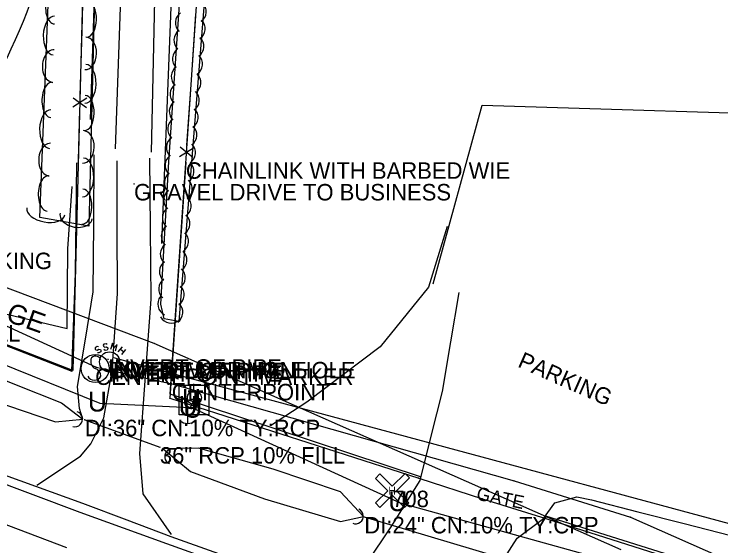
# Model space of a CAD drawing. Extents: x 1441650 to 1491889, y 345904 to 358319.
# Drawn here: x 1445767.6 to 1445982.1, y 354579.8 to 354741.3 of the extents above; entities that cross this region are included whole.
import ezdxf

# ---------------------------------------------------------------- set-up
doc = ezdxf.new("R2010")
doc.units = 0
for name, color, linetype in [('Default', 7, 'Continuous'), ('S_CROSS_DRAIN', 7, 'Continuous'), ('S_CROSS_DRAIN_ANNOT', 7, 'Continuous'), ('S_DITCHLINE', 7, 'Continuous'), ('S_DRG_PT_SYM', 7, 'Continuous'), ('S_EDGE_PAVEMENT', 7, 'Continuous'), ('S_FENCE', 7, 'Continuous'), ('S_FENCE_ANNOT', 7, 'Continuous'), ('S_GAS_UTILITIES', 7, 'Continuous'), ('S_GAS_UTILITIES_ANNOT', 7, 'Continuous'), ('S_GATE_ANNOT', 7, 'Continuous'), ('S_GRAVEL_ROAD', 7, 'Continuous'), ('S_MANHOLE_ANNOT', 7, 'Continuous'), ('S_MISC_BOUNDARY_ANNOT', 7, 'Continuous'), ('S_MSC_PT_SYM', 7, 'Continuous'), ('S_PARKING', 7, 'Continuous'), ('S_PARKING_ANNOT', 7, 'Continuous'), ('S_PAVEMENT_CROWN', 7, 'Continuous'), ('S_PHOTO_CTL', 7, 'Continuous'), ('S_PHOTO_CTL_ANNOT', 7, 'Continuous'), ('S_SANITARY_SEWER', 7, 'Continuous'), ('S_SANITARY_SEWER_ANNOT', 7, 'Continuous'), ('S_SHOULDER', 7, 'Continuous'), ('S_SIGN', 7, 'Continuous'), ('S_SIGN_ANNOT', 7, 'Continuous'), ('S_STREAM', 7, 'Continuous'), ('S_SURVEY_TEXT_ANNOT', 7, 'Continuous'), ('S_TELEPHONE_UTILITIES', 7, 'Continuous'), ('S_TREE', 7, 'Continuous'), ('S_UNDERGROUND_CABLE', 7, 'Continuous'), ('S_UTILITY_POLE', 7, 'Continuous'), ('S_UTL_PT_SYM', 7, 'Continuous'), ('S_WATER_UTILITIES', 7, 'Continuous')]:
    doc.layers.add(name, color=color, linetype=linetype)

msp = doc.modelspace()

# ---------------------------------------------------------------- linework, layer by layer
at = {"layer": 'S_CROSS_DRAIN'}
for p, q in [((1445789.02, 354618.12), (1445811.83, 354609.8)), ((1445873.89, 354588.6), (1445920.32, 354574.73))]:
    msp.add_line(p, q, dxfattribs=at)
for centre, start, end in [((1445786.07, 354618.31), 254.2844, 74.6136), ((1445815.59, 354606.93), 68.2155, 248.5447), ((1445871.28, 354588.81), 246.6814, 67.0106)]:
    msp.add_arc(centre, 2.3, start, end, dxfattribs=at)
at = {"layer": 'S_DITCHLINE'}
for points in [[(1445788.43, 354618.25), (1445787.46, 354621.49), (1445786.82, 354628.25), (1445789.21, 354642.59), (1445791.61, 354656.92), (1445791.77, 354677.73), (1445791.93, 354698.55)], [(1445718.48, 354646.49), (1445724.35, 354644.58), (1445738.95, 354639.6), (1445753.55, 354634.61), (1445767.74, 354628.93), (1445781.94, 354623.24), (1445788.45, 354618.24)], [(1445718.49, 354646.49), (1445722.92, 354641.68), (1445736.93, 354634.55), (1445750.94, 354627.42), (1445765.53, 354622.43), (1445780.12, 354617.44), (1445788.4, 354618.25)]]:
    msp.add_lwpolyline(points, dxfattribs=at)
msp.add_lwpolyline([(1445812.85, 354609.24), (1445821.09, 354602.4), (1445843.54, 354594.09), (1445866.61, 354587.17), (1445873.64, 354588.7), (1445866.68, 354596.26), (1445846.24, 354603.09), (1445823.57, 354609.53)], close=True, dxfattribs=at)
at = {"layer": 'S_DRG_PT_SYM'}
for points in [[(1445789.02, 354618.12), (1445789.02, 354618.17), (1445789.02, 354618.12), (1445788.97, 354618.12), (1445789.02, 354618.12), (1445789.02, 354618.07), (1445789.02, 354618.12), (1445789.07, 354618.12)], [(1445811.83, 354609.8), (1445811.83, 354609.85), (1445811.83, 354609.8), (1445811.78, 354609.8), (1445811.83, 354609.8), (1445811.83, 354609.75), (1445811.83, 354609.8), (1445811.88, 354609.8)], [(1445873.89, 354588.6), (1445873.89, 354588.65), (1445873.89, 354588.6), (1445873.84, 354588.6), (1445873.89, 354588.6), (1445873.89, 354588.55), (1445873.89, 354588.6), (1445873.94, 354588.6)]]:
    msp.add_lwpolyline(points, dxfattribs=at)
at = {"layer": 'S_EDGE_PAVEMENT'}
msp.add_lwpolyline([(1445758.93, 354600.82), (1445773.25, 354595.45), (1445787.57, 354590.09), (1445800.71, 354585.31), (1445813.85, 354580.52), (1445828.54, 354575.32)], dxfattribs=at)
at = {"layer": 'S_FENCE'}
for p, q in [((1445789.61, 354715.73), (1445785.44, 354712.97)), ((1445785.51, 354715.84), (1445789.53, 354712.87)), ((1445817.79, 354698.06), (1445822.07, 354700.64)), ((1445821.87, 354697.78), (1445817.98, 354700.92)), ((1445819.73, 354696.27), (1445814.87, 354624.65)), ((1445786.23, 354662.58), (1445786.63, 354696.05)), ((1445785.12, 354632.89), (1445786.23, 354662.58)), ((1445717.1, 354659.39), (1445785.12, 354632.89)), ((1445814.87, 354624.65), (1445890.4, 354600.42)), ((1445890.4, 354600.42), (1445909.74, 354594.09)), ((1445909.74, 354594.09), (1445929.03, 354588.1)), ((1445929.03, 354588.1), (1446032.54, 354555.34))]:
    msp.add_line(p, q, dxfattribs=at)
for points in [[(1445790.41, 354824.29), (1445785.39, 354633.02), (1445717.16, 354659.61)], [(1445891.24, 354600.72), (1445814.94, 354625.84), (1445824.57, 354767.69), (1445980.66, 354766.35)], [(1445788.62, 354756.33), (1445788.1, 354736.34)], [(1445821.42, 354721.3), (1445822.77, 354741.25)], [(1445788.1, 354736.34), (1445787.57, 354716.35)], [(1445820.06, 354701.34), (1445821.42, 354721.3)], [(1445787.47, 354712.35), (1445787.06, 354696.95)], [(1446086.26, 354539.37), (1445928.95, 354588.88)]]:
    msp.add_lwpolyline(points, dxfattribs=at)
at = {"layer": 'S_GAS_UTILITIES'}
for p, q in [((1445467.8, 354783.19), (1445792.48, 354634.07)), ((1445792.48, 354634.07), (1445815.43, 354629)), ((1445815.43, 354629), (1445919.33, 354599.56)), ((1445919.33, 354599.56), (1445954.67, 354588.57)), ((1445954.67, 354588.57), (1445989.77, 354573.1))]:
    msp.add_line(p, q, dxfattribs=at)
at = {"layer": 'S_GRAVEL_ROAD'}
for points in [[(1445809.25, 354699.37), (1445810.78, 354768.8), (1445812.32, 354864.17)], [(1445802.23, 354856.45), (1445800.36, 354760.69), (1445798.21, 354700.41)], [(1445774.44, 354598.22), (1445787.76, 354607.08), (1445790.89, 354610.81), (1445794.79, 354618.66), (1445797.37, 354633.08), (1445798.94, 354656.43), (1445798.88, 354676.57), (1445798.82, 354696.71)], [(1445815.36, 354583.24), (1445806.71, 354595.59), (1445805.78, 354607.86), (1445807.46, 354631.31), (1445809.15, 354654.76), (1445808.95, 354676.16), (1445808.75, 354697.56)], [(1445718.48, 354666.76), (1445739.25, 354656.29), (1445761.44, 354651.06), (1445783.64, 354645.82), (1445783.92, 354670.01), (1445785.2, 354688.95)], [(1445866.75, 354564.96), (1445874.66, 354574.6), (1445882, 354585.59), (1445890.82, 354599.62), (1445894.2, 354613.15), (1445897.58, 354626.67), (1445900.15, 354641.73), (1445902.71, 354656.79)], [(1445919.97, 354547.38), (1445916.01, 354559.79), (1445916.32, 354575.94), (1445920.32, 354582.13), (1445928.28, 354588.08), (1445931.72, 354592.89), (1445938.4, 354594.75), (1445942.86, 354593.76), (1445956.94, 354590.17), (1445971.03, 354586.57), (1445985.12, 354582.98), (1445999.2, 354579.38), (1446018.14, 354575.85), (1446037.08, 354572.32), (1446051.94, 354570.3), (1446066.81, 354568.29), (1446081.67, 354566.27), (1446096.54, 354564.25), (1446111, 354561.07), (1446125.47, 354557.89)]]:
    msp.add_lwpolyline(points, dxfattribs=at)
at = {"layer": 'S_MSC_PT_SYM'}
for points in [[(1445786.63, 354696.05), (1445786.63, 354696.1), (1445786.63, 354696.05), (1445786.58, 354696.05), (1445786.63, 354696.05), (1445786.63, 354696), (1445786.63, 354696.05), (1445786.68, 354696.05)], [(1445819.73, 354696.27), (1445819.73, 354696.32), (1445819.73, 354696.27), (1445819.68, 354696.27), (1445819.73, 354696.27), (1445819.73, 354696.22), (1445819.73, 354696.27), (1445819.78, 354696.27)], [(1445803.99, 354689.7), (1445803.99, 354689.75), (1445803.99, 354689.7), (1445803.94, 354689.7), (1445803.99, 354689.7), (1445803.99, 354689.65), (1445803.99, 354689.7), (1445804.04, 354689.7)], [(1445786.23, 354662.58), (1445786.23, 354662.63), (1445786.23, 354662.58), (1445786.18, 354662.58), (1445786.23, 354662.58), (1445786.23, 354662.53), (1445786.23, 354662.58), (1445786.28, 354662.58)], [(1445785.12, 354632.89), (1445785.12, 354632.94), (1445785.12, 354632.89), (1445785.07, 354632.89), (1445785.12, 354632.89), (1445785.12, 354632.84), (1445785.12, 354632.89), (1445785.17, 354632.89)], [(1445814.87, 354624.65), (1445814.87, 354624.7), (1445814.87, 354624.65), (1445814.82, 354624.65), (1445814.87, 354624.65), (1445814.87, 354624.6), (1445814.87, 354624.65), (1445814.92, 354624.65)], [(1445890.4, 354600.42), (1445890.4, 354600.47), (1445890.4, 354600.42), (1445890.35, 354600.42), (1445890.4, 354600.42), (1445890.4, 354600.37), (1445890.4, 354600.42), (1445890.45, 354600.42)], [(1445909.74, 354594.09), (1445909.74, 354594.14), (1445909.74, 354594.09), (1445909.69, 354594.09), (1445909.74, 354594.09), (1445909.74, 354594.04), (1445909.74, 354594.09), (1445909.79, 354594.09)], [(1445929.03, 354588.1), (1445929.03, 354588.15), (1445929.03, 354588.1), (1445928.98, 354588.1), (1445929.03, 354588.1), (1445929.03, 354588.05), (1445929.03, 354588.1), (1445929.08, 354588.1)]]:
    msp.add_lwpolyline(points, dxfattribs=at)
at = {"layer": 'S_PARKING'}
msp.add_lwpolyline([(1445894.76, 354659.33), (1445909.68, 354713.61), (1446020.86, 354710.14)], dxfattribs=at)
msp.add_ellipse((1445590.08, 354813.05), major_axis=(128.22, 146.75), ratio=0.999981, start_param=4.605684, end_param=5.103888, dxfattribs=at)
at = {"layer": 'S_PAVEMENT_CROWN'}
msp.add_lwpolyline([(1445754.09, 354590.41), (1445768.79, 354584.89), (1445783.49, 354579.36)], dxfattribs=at)
at = {"layer": 'S_PHOTO_CTL'}
for p, q in [((1445877.25, 354600.31), (1445878.61, 354601.66)), ((1445878.61, 354601.66), (1445882.35, 354597.92)), ((1445882.35, 354597.92), (1445886.25, 354601.82)), ((1445886.25, 354601.82), (1445887.6, 354600.47)), ((1445880.99, 354596.57), (1445877.25, 354600.31)), ((1445887.6, 354600.47), (1445883.7, 354596.57)), ((1445877.25, 354592.84), (1445880.99, 354596.57)), ((1445883.7, 354596.57), (1445887.44, 354592.84)), ((1445882.34, 354595.22), (1445878.61, 354591.48)), ((1445886.08, 354591.48), (1445882.34, 354595.22)), ((1445878.61, 354591.48), (1445877.25, 354592.84)), ((1445887.44, 354592.84), (1445886.08, 354591.48))]:
    msp.add_line(p, q, dxfattribs=at)
at = {"layer": 'S_SANITARY_SEWER'}
for p, q in [((1445792.78, 354640.37), (1445792.23, 354639.98)), ((1445793.2, 354640.29), (1445792.78, 354640.37)), ((1445792.23, 354639.98), (1445792.16, 354639.59)), ((1445792.16, 354639.59), (1445792.35, 354639.32)), ((1445792.35, 354639.32), (1445792.78, 354639.21)), ((1445792.78, 354639.21), (1445793.32, 354639.55)), ((1445793.32, 354638.39), (1445792.93, 354638.47)), ((1445793.32, 354639.55), (1445793.78, 354639.48)), ((1445793.86, 354638.78), (1445793.32, 354638.39)), ((1445793.78, 354639.48), (1445793.94, 354639.21)), ((1445793.94, 354639.21), (1445793.86, 354638.78)), ((1445799.21, 354638.74), (1445800.45, 354640.21)), ((1445799.87, 354639.52), (1445800.84, 354638.7)), ((1445801.42, 354639.4), (1445800.18, 354637.93)), ((1445798.06, 354636.92), (1446371.19, 354482.39))]:
    msp.add_line(p, q, dxfattribs=at)
for points in [[(1445795.88, 354640.91), (1445795.53, 354641.18), (1445794.87, 354641.1), (1445794.64, 354640.76), (1445794.67, 354640.45), (1445795.02, 354640.14), (1445795.64, 354640.25), (1445796.03, 354639.94), (1445796.07, 354639.63), (1445795.8, 354639.24), (1445795.18, 354639.17), (1445794.83, 354639.44)], [(1445798.32, 354639.05), (1445798.86, 354640.91), (1445797.81, 354639.9), (1445797.43, 354641.34), (1445796.88, 354639.48)]]:
    msp.add_lwpolyline(points, dxfattribs=at)
msp.add_circle((1445796.56, 354635.68), 3.05, dxfattribs=at)
at = {"layer": 'S_SHOULDER'}
msp.add_lwpolyline([(1445759.69, 354603.15), (1445774.03, 354597.98), (1445788.37, 354592.81), (1445801.79, 354587.73), (1445815.2, 354582.66), (1445829.6, 354577.51)], dxfattribs=at)
at = {"layer": 'S_SIGN'}
msp.add_circle((1445792.2, 354633.68), 4.24, dxfattribs=at)
for centre, radius, start, end in [((1445793.37, 354635.93), 2.55, 167.1196, 241.9813), ((1445792.33, 354635.84), 1.62, 16.5258, 156.8957), ((1445791.5, 354631.4), 2.38, 358.6529, 73.7063), ((1445791.94, 354632.28), 2.17, 204.641, 335.359)]:
    msp.add_arc(centre, radius, start, end, dxfattribs=at)
at = {"layer": 'S_STREAM'}
for points in [[(1445790.79, 354709.29), (1445794.12, 354810.87)], [(1445812.41, 354671.58), (1445817.58, 354802.35)], [(1445899.02, 354676.78), (1445893.35, 354658.37), (1445878.66, 354640.27), (1445856.49, 354623.48), (1445845.71, 354616.47)]]:
    msp.add_lwpolyline(points, dxfattribs=at)
at = {"layer": 'S_TELEPHONE_UTILITIES'}
msp.add_lwpolyline([(1445817.65, 354619.57), (1445817.65, 354628.57), (1445826.65, 354628.57), (1445826.65, 354619.57)], close=True, dxfattribs=at)
at = {"layer": 'S_TREE'}
for points in [[(1446000.72, 354764.17), (1445826.85, 354765.13), (1445817.58, 354647.96), (1445813.11, 354648.8), (1445812.14, 354653.17), (1445814.51, 354696.38), (1445819.04, 354762.24), (1445822, 354804.32)], [(1445793.13, 354791.1), (1445790.28, 354676.85), (1445775.38, 354679.55), (1445779.72, 354790.62), (1445784.18, 354795.72), (1445791.44, 354793.19), (1445792.72, 354789.89)]]:
    msp.add_lwpolyline(points, dxfattribs=at)
for centre, major_axis, ratio, start_param, end_param in [((1445780.01, 354743.63), (-0.21, -5.34), 0.540516, 3.141885, 6.283478), ((1445789.72, 354739.65), (0.13, 5.34), 0.540472, 3.141593, 6.283185), ((1445822.29, 354742.07), (0.29, 3.63), 0.999988, 3.825789, 5.598989), ((1445820.16, 354738.67), (-0.25, -3.63), 0.999988, 3.825788, 5.598989), ((1445779.66, 354734.77), (-0.23, -5.86), 0.549893, 3.141895, 6.283487), ((1445821.94, 354736.8), (0.29, 3.63), 0.999988, 3.825789, 5.598989), ((1445819.72, 354733.35), (-0.25, -3.63), 0.999988, 3.825788, 5.598989), ((1445789.21, 354729.36), (0.12, 4.95), 0.685023, 3.141593, 6.283185), ((1445821.56, 354731.51), (0.29, 3.63), 0.999988, 3.825789, 5.598989), ((1445779.56, 354725.51), (-0.2, -4.95), 0.685078, 3.142087, 6.28368), ((1445819.3, 354727.72), (-0.25, -3.63), 0.999988, 3.825789, 5.598989), ((1445821.13, 354726.08), (0.29, 3.63), 0.999988, 3.825789, 5.598989), ((1445789.24, 354720.1), (0.15, 5.87), 0.549849, 3.141593, 6.283185), ((1445818.92, 354722.29), (-0.25, -3.63), 0.999988, 3.825789, 5.598989), ((1445820.65, 354720.46), (0.29, 3.63), 0.999988, 3.825789, 5.598989), ((1445778.9, 354715.23), (-0.21, -5.34), 0.540516, 3.141885, 6.283478), ((1445818.59, 354717), (-0.25, -3.63), 0.999988, 3.825789, 5.598989), ((1445820.16, 354715.14), (0.29, 3.63), 0.999988, 3.825789, 5.598989), ((1445789.02, 354711.24), (0.13, 5.34), 0.540472, 3.141593, 6.283185), ((1445818.3, 354711.72), (-0.25, -3.63), 0.999988, 3.825788, 5.598989), ((1445778.55, 354706.37), (-0.23, -5.86), 0.549893, 3.141895, 6.283487), ((1445819.81, 354709.87), (0.29, 3.63), 0.999988, 3.825789, 5.598989), ((1445817.86, 354706.4), (-0.25, -3.63), 0.999988, 3.825788, 5.598989), ((1445819.43, 354704.58), (0.29, 3.63), 0.999988, 3.825789, 5.598989), ((1445788.5, 354700.94), (0.12, 4.95), 0.685023, 3.141593, 6.283185), ((1445817.44, 354700.77), (-0.25, -3.63), 0.999988, 3.825789, 5.598989), ((1445778.45, 354697.11), (-0.2, -4.95), 0.685078, 3.142087, 6.28368), ((1445819, 354699.16), (0.29, 3.63), 0.999988, 3.825789, 5.598989), ((1445817.08, 354695.38), (-0.2, -3.64), 0.999989, 3.825789, 5.598989), ((1445788.53, 354691.68), (0.15, 5.87), 0.549849, 3.141593, 6.283185), ((1445818.52, 354693.53), (0.29, 3.63), 0.999988, 3.825789, 5.598989), ((1445777.79, 354686.83), (-0.21, -5.34), 0.540516, 3.141885, 6.283478), ((1445816.83, 354690.08), (-0.2, -3.64), 0.999989, 3.825788, 5.598989), ((1445818.03, 354688.22), (0.29, 3.63), 0.999988, 3.825789, 5.598989), ((1445788.31, 354682.82), (0.13, 5.34), 0.540472, 3.141593, 6.283185), ((1445816.61, 354684.8), (-0.2, -3.64), 0.999989, 3.825788, 5.598989), ((1445817.68, 354682.95), (0.29, 3.63), 0.999988, 3.825789, 5.598989), ((1445777.24, 354681.37), (5.77, -1.05), 0.550316, 3.141365, 6.282957), ((1445816.25, 354679.48), (-0.2, -3.64), 0.999989, 3.825788, 5.598989), ((1445786.4, 354679.97), (4.87, -0.88), 0.685605, 3.141219, 6.282812), ((1445817.3, 354677.66), (0.29, 3.63), 0.999988, 3.825789, 5.598989), ((1445815.91, 354673.85), (-0.2, -3.64), 0.999989, 3.825789, 5.598989), ((1445816.87, 354672.23), (0.29, 3.63), 0.999988, 3.825789, 5.598989), ((1445815.61, 354668.41), (-0.2, -3.64), 0.999989, 3.825789, 5.598989), ((1445816.39, 354666.61), (0.29, 3.63), 0.999988, 3.825789, 5.598989), ((1445815.35, 354663.11), (-0.2, -3.64), 0.999989, 3.825788, 5.598989), ((1445815.9, 354661.29), (0.29, 3.63), 0.999988, 3.825789, 5.598989), ((1445815.14, 354657.84), (-0.2, -3.64), 0.999989, 3.825788, 5.598989), ((1445815.55, 354656.02), (0.29, 3.63), 0.999988, 3.825789, 5.598989), ((1445814.85, 354653.24), (0.79, -3.56), 0.999997, 3.825788, 5.598989), ((1445815.17, 354650.73), (0.29, 3.63), 0.999988, 3.825789, 5.598989), ((1445815.25, 354651.07), (3.34, 1.46), 0.99996, 3.22727, 5.00047)]:
    msp.add_ellipse(centre, major_axis=major_axis, ratio=ratio, start_param=start_param, end_param=end_param, dxfattribs=at)
at = {"layer": 'S_UNDERGROUND_CABLE'}
for p, q in [((1445715.14, 354654.84), (1445793.58, 354623.14)), ((1445793.58, 354623.14), (1445821.11, 354621.82)), ((1445821.11, 354621.82), (1445822.14, 354623.94)), ((1445822.14, 354623.94), (1445822.54, 354621.28)), ((1445822.54, 354621.28), (1445884.75, 354592.91)), ((1445884.75, 354592.91), (1446003.57, 354559.96))]:
    msp.add_line(p, q, dxfattribs=at)
at = {"layer": 'S_UTILITY_POLE'}
for p, q in [((1445822.17, 354626.93), (1445822.17, 354629.04)), ((1445820.23, 354621.68), (1445820.23, 354616.95))]:
    msp.add_line(p, q, dxfattribs=at)
msp.add_circle((1445822.3, 354624.79), 2.13, dxfattribs=at)
msp.add_arc((1445820.29, 354620.38), 3.41, 226.3972, 313.6028, dxfattribs=at)
at = {"layer": 'S_UTL_PT_SYM'}
for points in [[(1445810, 354641.4), (1445810, 354641.45), (1445810, 354641.4), (1445809.95, 354641.4), (1445810, 354641.4), (1445810, 354641.35), (1445810, 354641.4), (1445810.05, 354641.4)], [(1445796.11, 354636.48), (1445796.11, 354636.53), (1445796.11, 354636.48), (1445796.06, 354636.48), (1445796.11, 354636.48), (1445796.11, 354636.43), (1445796.11, 354636.48), (1445796.16, 354636.48)], [(1445798.06, 354636.92), (1445798.06, 354636.97), (1445798.06, 354636.92), (1445798.01, 354636.92), (1445798.06, 354636.92), (1445798.06, 354636.87), (1445798.06, 354636.92), (1445798.11, 354636.92)], [(1445792.48, 354634.07), (1445792.48, 354634.12), (1445792.48, 354634.07), (1445792.43, 354634.07), (1445792.48, 354634.07), (1445792.48, 354634.02), (1445792.48, 354634.07), (1445792.53, 354634.07)], [(1445796.31, 354634.66), (1445796.31, 354634.71), (1445796.31, 354634.66), (1445796.26, 354634.66), (1445796.31, 354634.66), (1445796.31, 354634.61), (1445796.31, 354634.66), (1445796.36, 354634.66)], [(1445796.56, 354635.68), (1445796.56, 354635.73), (1445796.56, 354635.68), (1445796.51, 354635.68), (1445796.56, 354635.68), (1445796.56, 354635.63), (1445796.56, 354635.68), (1445796.61, 354635.68)], [(1445797.48, 354635.42), (1445797.48, 354635.47), (1445797.48, 354635.42), (1445797.43, 354635.42), (1445797.48, 354635.42), (1445797.48, 354635.37), (1445797.48, 354635.42), (1445797.53, 354635.42)], [(1445815.43, 354629), (1445815.43, 354629.05), (1445815.43, 354629), (1445815.38, 354629), (1445815.43, 354629), (1445815.43, 354628.95), (1445815.43, 354629), (1445815.48, 354629)], [(1445919.33, 354599.56), (1445919.33, 354599.61), (1445919.33, 354599.56), (1445919.28, 354599.56), (1445919.33, 354599.56), (1445919.33, 354599.51), (1445919.33, 354599.56), (1445919.38, 354599.56)], [(1445954.67, 354588.57), (1445954.67, 354588.62), (1445954.67, 354588.57), (1445954.62, 354588.57), (1445954.67, 354588.57), (1445954.67, 354588.52), (1445954.67, 354588.57), (1445954.72, 354588.57)]]:
    msp.add_lwpolyline(points, dxfattribs=at)
at = {"layer": 'S_WATER_UTILITIES'}
for p, q in [((1445620.33, 354712.97), (1445810, 354641.4)), ((1445810, 354641.4), (1445951.8, 354578.69))]:
    msp.add_line(p, q, dxfattribs=at)

# ---------------------------------------------------------------- texts
at = {"layer": 'Default'}
for p in [(1445789.96, 354620.6), (1445817.48, 354619.28), (1445818.52, 354621.4), (1445818.91, 354618.74), (1445881.12, 354590.37)]:
    msp.add_text('U', height=6, rotation=360, dxfattribs=at).set_placement(p)
at = {"layer": 'S_CROSS_DRAIN_ANNOT'}
for s, p in [('36" CMP 10 FILL', (1445718.47, 354641.83)), ('DI:36" CN:10% TY:RCP', (1445789.02, 354613.12)), ('36" RCP 10% FILL', (1445811.83, 354604.8)), ('DI:24" CN:10% TY:CPP', (1445873.89, 354583.6))]:
    msp.add_text(s, height=5, dxfattribs=at).set_placement(p)
at = {"layer": 'S_FENCE_ANNOT'}
msp.add_text('CHAINLINK WITH BARBED WIE', height=5, dxfattribs=at).set_placement((1445819.73, 354691.27))
at = {"layer": 'S_GAS_UTILITIES_ANNOT'}
msp.add_text('CENTERPOINT', height=5, dxfattribs=at).set_placement((1445815.43, 354624))
at = {"layer": 'S_GATE_ANNOT'}
msp.add_text('GATE', height=4, rotation=348.4503, dxfattribs=at).set_placement((1445907.7, 354593.88))
at = {"layer": 'S_MANHOLE_ANNOT'}
for s in ['TOP OF MANHOLE', 'BOTTOM OF MANHOLE']:
    msp.add_text(s, height=5, dxfattribs=at).set_placement((1445796.56, 354630.68))
at = {"layer": 'S_MISC_BOUNDARY_ANNOT'}
msp.add_text('OPEN STORAGE', height=6.0004, rotation=340.3614, dxfattribs=at).set_placement((1445715.22, 354665.86))
at = {"layer": 'S_PARKING_ANNOT'}
msp.add_text('PARKING', height=5, rotation=336.2007, dxfattribs=at).set_placement((1445920.16, 354634.3))
at = {"layer": 'S_PHOTO_CTL'}
msp.add_text('H', height=2.4, rotation=360, dxfattribs=at).set_placement((1445881.17, 354595.37))
at = {"layer": 'S_PHOTO_CTL_ANNOT'}
msp.add_text('708', height=5, dxfattribs=at).set_placement((1445882.34, 354591.57))
at = {"layer": 'S_SANITARY_SEWER_ANNOT'}
for p in [(1445796.11, 354631.48), (1445796.31, 354629.66), (1445797.48, 354630.42)]:
    msp.add_text('INVERT OF PIPE', height=5, dxfattribs=at).set_placement(p)
at = {"layer": 'S_SIGN_ANNOT'}
msp.add_text('CENTREPOINT MARKER', height=5, dxfattribs=at).set_placement((1445792.2, 354628.68))
at = {"layer": 'S_SURVEY_TEXT_ANNOT'}
for s, p in [('GRAVEL DRIVE TO BUSINESS', (1445803.99, 354684.7)), ('TO GRAVEL PARKING', (1445708.86, 354663.85))]:
    msp.add_text(s, height=5, dxfattribs=at).set_placement(p)
at = {"layer": 'S_TELEPHONE_UTILITIES'}
msp.add_text('T', height=6, rotation=360, dxfattribs=at).set_placement((1445820.21, 354621.07))

doc.saveas('drawing.dxf')
